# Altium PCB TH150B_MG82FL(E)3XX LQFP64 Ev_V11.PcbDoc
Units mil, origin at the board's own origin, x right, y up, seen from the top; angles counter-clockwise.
Board outline 2850 x 2110 mil, 2 copper layers (Top Layer, Bottom Layer); 50 components, 79 nets, 342 pads, 113 vias.
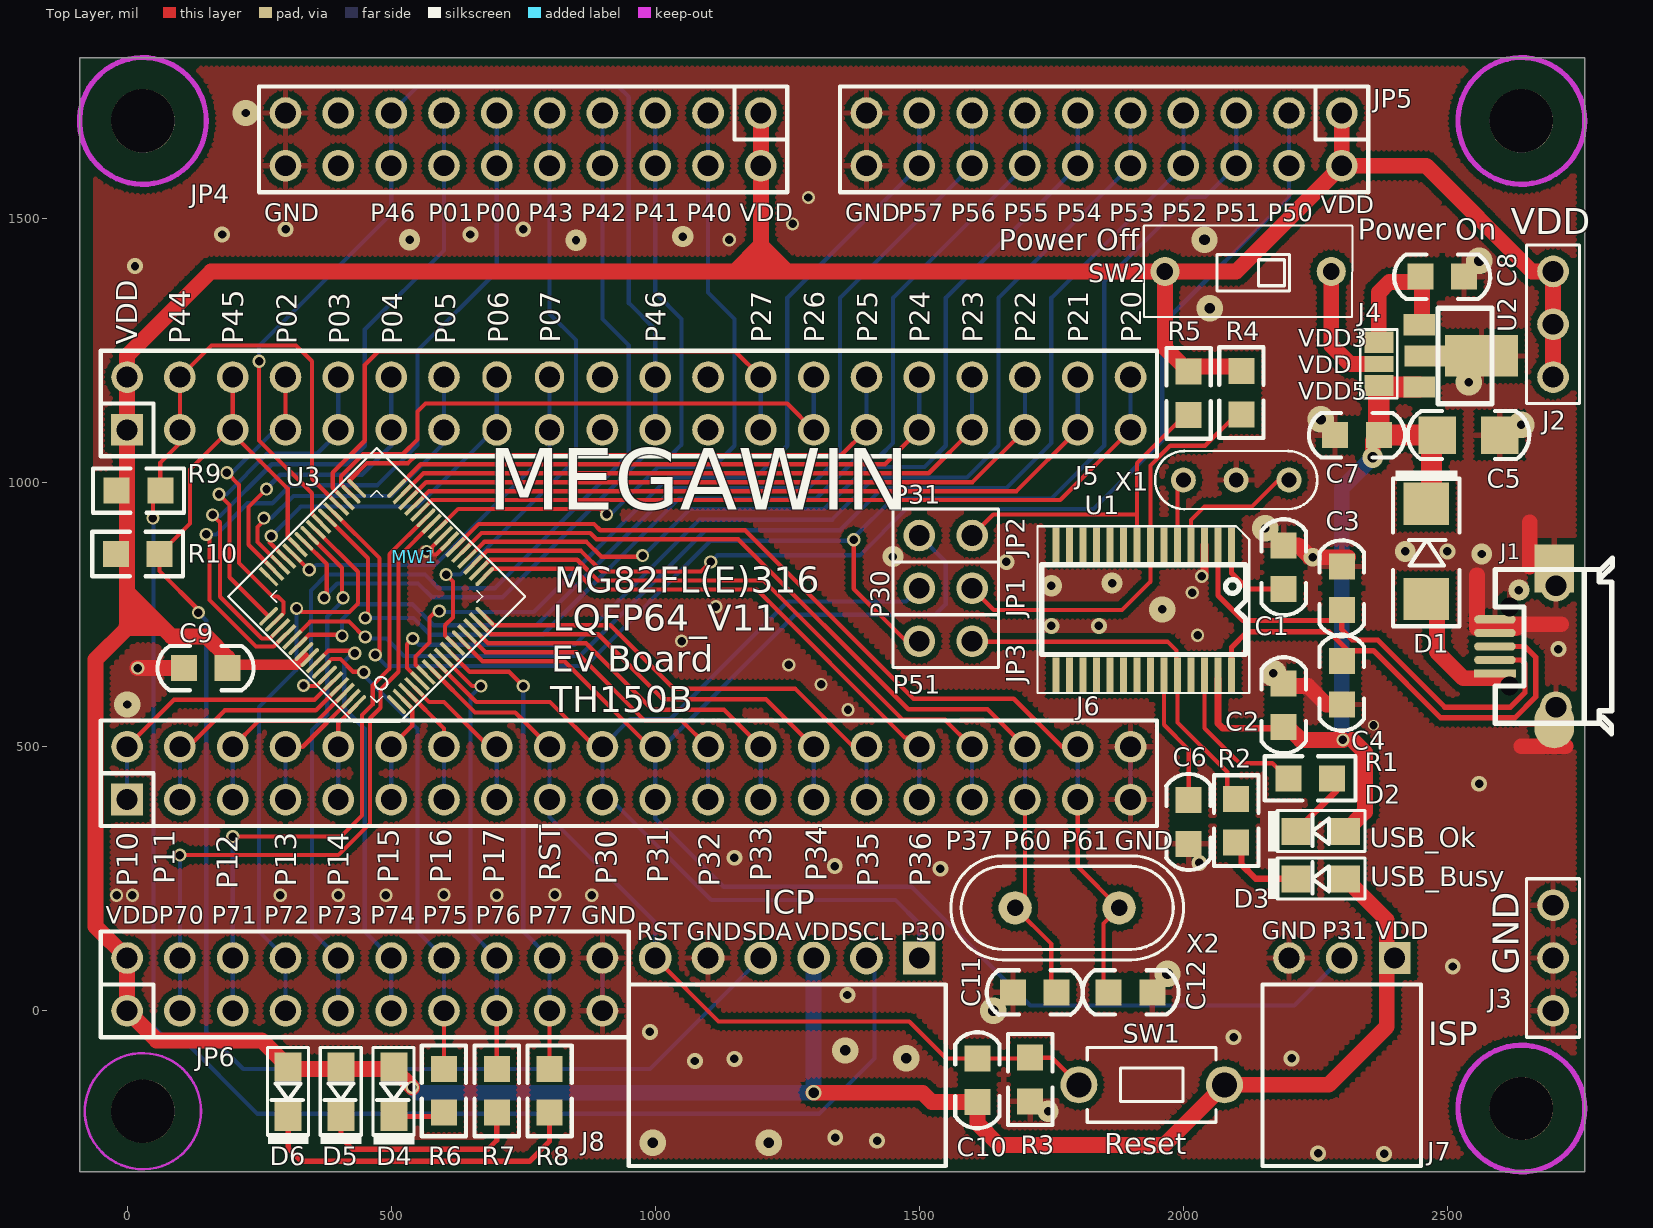
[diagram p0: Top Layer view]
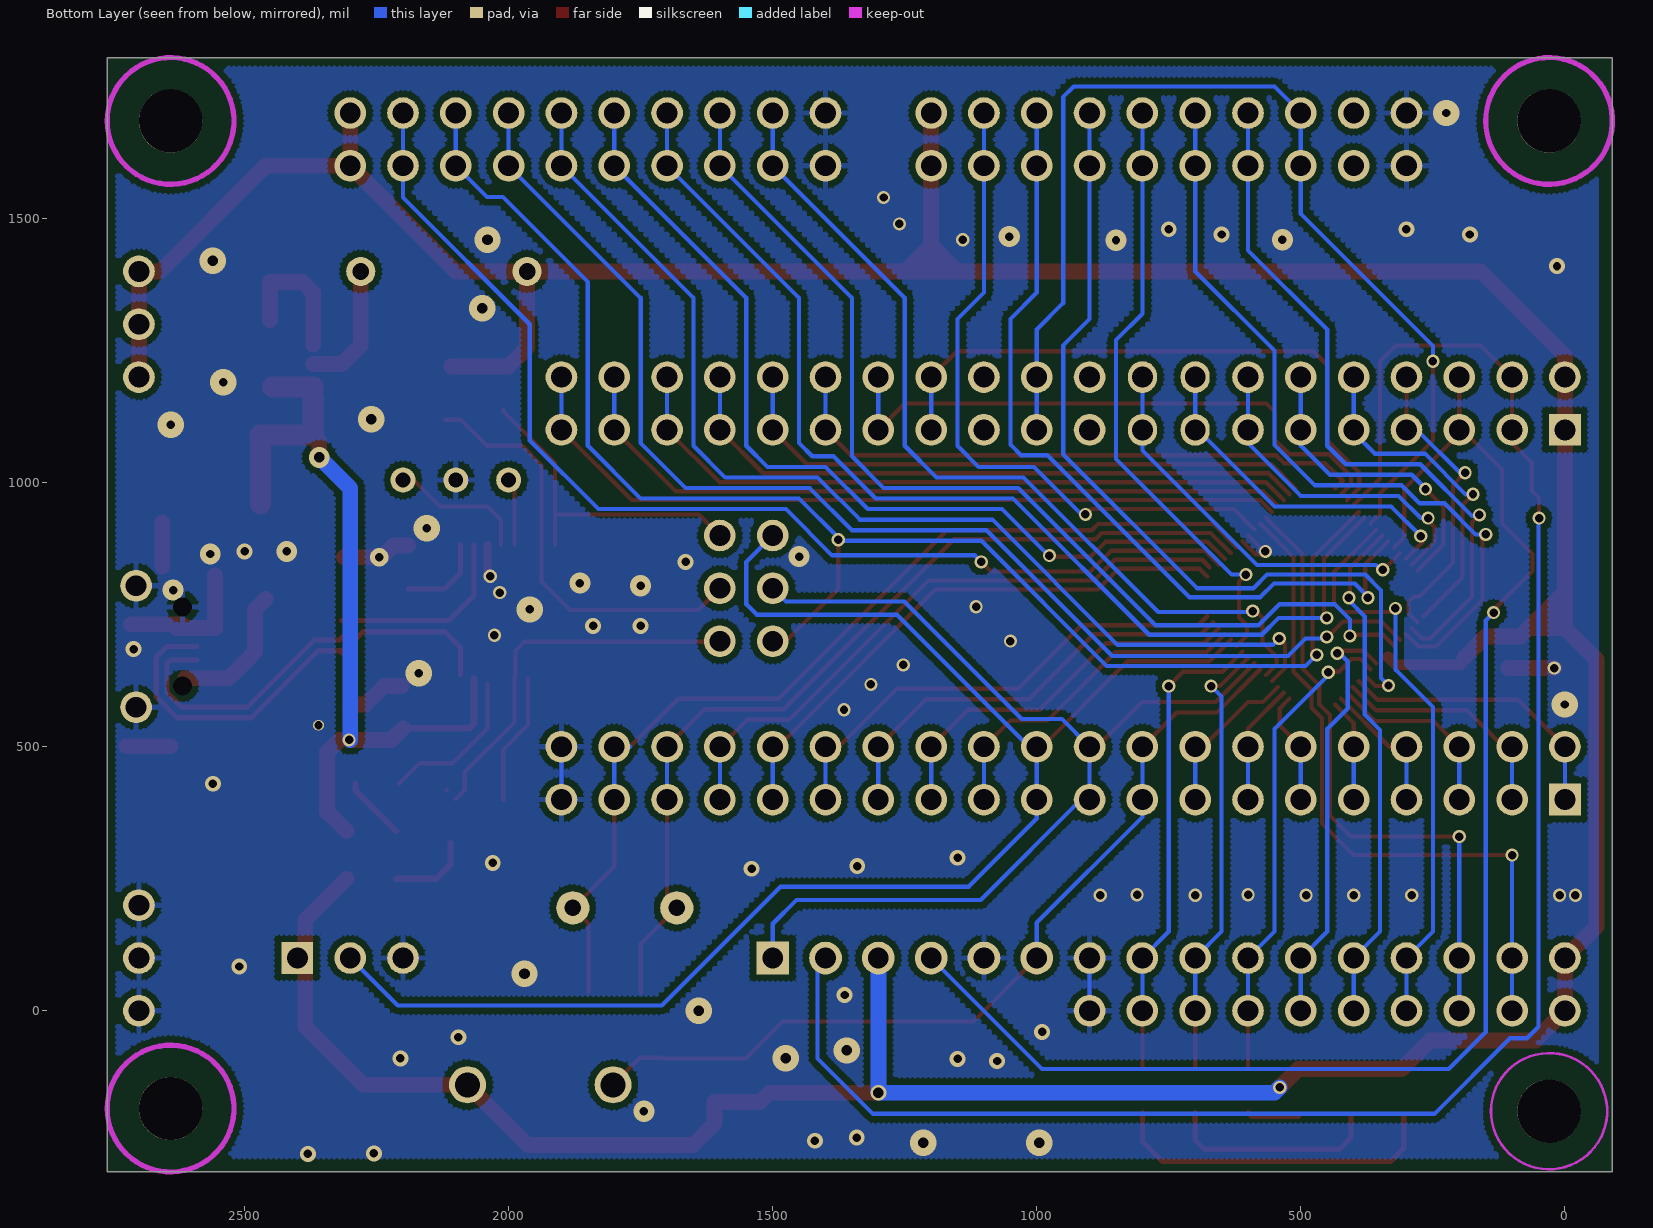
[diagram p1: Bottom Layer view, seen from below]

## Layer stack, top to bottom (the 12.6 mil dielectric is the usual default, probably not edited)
Top Layer: signal copper 1.4
Dielectric: dielectric 12.6, FR-4, Dk 4.8
Bottom Layer: signal copper 1.4

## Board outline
-90,-305 -90,1805 2760,1805 2760,-305

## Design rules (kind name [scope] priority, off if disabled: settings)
Clearance 12 [All] p1 off: gap=12
Clearance 10 [All] p2 off: gap=10
Clearance 6 [All] p3: gap=6
ComponentClearance [All] p1 off: gap=10 collisioncheckmode=3 verticalgap=10 showdistances=FALSE
HoleSize [All] p1: absolutevalues=TRUE maxlimit=500 minlimit=1 maxpercent=80.000 minpercent=20.000
MinimumSolderMaskSliver [All] p1 off: minsoldermaskwidth=10
PolygonConnect VIA [ISVIA] p1: connectstyle=Direct reliefconductorwidth=10 reliefentries=4 polygonreliefangle="90 Angle"
PolygonConnect [All] p2: connectstyle=Relief reliefconductorwidth=10 reliefentries=4 polygonreliefangle="90 Angle"
RoomDefinition "TH150B_MG82FL(E)3XX LQFP64 Ev_V10" [InComponentClass('TH150B_MG82FL(E)3XX LQFP64 Ev_V10')] p1: confinementstyle=ConfineIn formatcopy=TRUE lockcomponents=FALSE outline -505,-825 3205,-825 3205,2185 -505,2185
RoutingVias [All] p1: holewidth=16 width=25 viastyle="Through Hole" minholewidth=16 minwidth=24 maxholewidth=28 maxwidth=50
SilkToSilkClearance [All] p1 off: silktosilkclearance=10
SilkscreenOverComponentPads [All] p1 off: minsilkscreentomaskgap=10
SolderMaskExpansion [All] p1 off: expansion=4
Width [All] p1: maxlimit=200 minlimit=6 preferedwidth=10
23 further rules are at their usual default settings.

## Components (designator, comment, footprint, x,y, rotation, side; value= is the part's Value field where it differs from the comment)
C1 "4.7uF" 0805C 2190,840 r90 top
C2 "0.1uF" 0805C 2190,578.66 r270 top
C3 "15pF" 0805C 2300,800 r90 top
C4 "15pF" 0805C 2300,621.34 r270 top
C5 "4.7uF" 1206C 2540,1090 r0 top
C6 "0.1uF" 0805C 2010,357.66 r90 top
C7 "0.1uF" 0805C 2328.66,1090 r180 top
C8 "4.7uF" 0805C 2490,1390 r0 top
C9 "0.1uF" 0805C 148.66,649 r180 top
C10 "1u" 0805C 1610,-131.34 r90 top
C11 "NC" 0805C 1718.66,35 r180 top
C12 "NC" 0805C 1900,35 r0 top
D1 "1N5817" D5817_SMD_1 2460,870 r270 top
D2 "Yellow" 0805D 2260,340 r180 top
D3 "RED" 0805D 2260,250 r180 top
D4 "Green" 0805D 505,-153.08 r270 top
D5 "RED" 0805D 405,-153.08 r270 top
D6 "Green" 0805D 305,-153.08 r270 top
J1 "Micro USB母座" JACK_USB_SMD290X220P065 2590,690 r180 top
J2 "*" PS3P254 2700,1200 r90 top
J3 "*" PS3P254 2700,200 r270 top
J4 "*" JUMP3_SMD 2370,1225 r90 top
J5 "*" PS20X2P254#1 0,1100 r0 top locked
J6 "*" PS20X2P254#2 0,400 r0 top locked
J7 "*" PS3P254f_90 2400,100 r180 top
J8 "*" PS6P254F_90 1500,100 r180 top
JP1 "JUMPER2" PS2P254 1500,800 r0 top
JP2 "JUMPER2" PS2P254 1500,900 r0 top
JP3 "JUMPER2" PS2P254 1500,700 r0 top
JP4 "*" PS10X2P254 1200,1700 r180 top
JP5 "*" PS10X2P254 2300,1700 r180 top
JP6 "*" PS10X2P254 0,0 r0 top
MW1 "MW-A4" MEGAWIN_T 543.33,860 r0 top
R1 "1K" 0805R 2240,440 r0 top
R2 "1K" 0805R 2100,360 r270 top
R3 "47K" 0805R 1710,-130 r90 top
R4 "4.7K" 0805R 2110,1170.46 r270 top
R5 "4.7K" 0805R 2010,1169.12 r270 top
R6 "1K" 0805R 600,-151.34 r270 top
R7 "1K" 0805R 700,-151.34 r270 top
R8 "1K" 0805R 800,-151.34 r270 top
R9 "4.7K" 0805R 21.66,985 r180 top
R10 "4.7K" 0805R 20,865 r180 top
SW1 "SW TACT-SPST" SW_T_2P 1940,-140 r180 top
SW2 "-" DIP2_SW 2280,1400 r180 top
U1 "MA101_TSSOP28" TSSOP28_170P065 1924.84,759.52 r180 top
U2 "AIC1734-33(SOT-89)" SOT89 2446.53,1240 r270 top
U3 "MG82Fx308/316(LQFP-64)" QFP64_7X7P040 472.58,784.62 r135 top locked (schematic designator U1)
X1 "6MHz" X3P 2200,1005 r180 top
X2 "NC" X49U 1780,195 r0 top

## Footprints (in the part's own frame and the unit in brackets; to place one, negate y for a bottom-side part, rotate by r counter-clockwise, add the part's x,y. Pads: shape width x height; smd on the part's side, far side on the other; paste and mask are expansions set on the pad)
0805C [mm]
  rect 1.25x1.25 smd: 1(-1.05,0) 2(1.05,0)
  silkscreen extent -2.31,-1.07 2.31,1.07
0805D [mm]
  rect 1.4x1.3 smd: 1(-1.192,0) 2(1.192,0)
  silkscreen extent -2.12,-1 2.53,0.98
0805R [mm]
  rect 1.25x1.25 smd: 1(-1.05,0) 2(1.05,0)
  silkscreen extent -2.18,-1.07 2.18,1.07
1206C [mm]
  rect 1.8x1.8 smd: 1(-1.5,0) 2(1.5,0)
  silkscreen extent -2.92,-1.15 2.92,1.16
D5817_SMD_1 [mil]
  rect 80x86.61 smd: 1(90,0) 2(-90,0)
  silkscreen extent -153,-63 142,63
DIP2_SW [mm]
  round 1.4 hole 0.8: 1(0,0) 2(8,0)
  silkscreen extent -1.02,-2.2 9.02,2.2
JACK_USB_SMD290X220P065 [mm]
  rect 1.9x1.8 on Mech2: 0(-2.85,-1.15) 0(-2.85,1.15)
  round 0.8 hole 0.9 unplated: 1(-0.7,1.9) 5(-0.7,-1.9)
  rect 2x0.4 smd: 1(0,1.3)
  oval 2x0.4 smd: 2(0,0.65) 3(0,0) 4(0,-0.65) 5(0,-1.3)
  round 1.524 hole 1: 5(-2.931,2.921) 5(-2.931,-2.921)
  oval 1.9x2.3 smd: 5(-2.85,3.75)
  rect 1.9x2.3 smd: 5(-2.85,-3.75)
  silkscreen extent -5.65,-4.25 -0.01,4.2
JUMP3_SMD [mil]
  rect 40x55 smd: 1(-41,0) 3(41,0)
  rect 30x55 smd: 2(0,0)
  silkscreen extent -65,-35 65,35
MEGAWIN_T [mil]
PS2P254 [mil]
  round 60 hole 39.37: 1(0,0) 2(100,0)
  silkscreen extent -50,-50 150,50
PS3P254 [mil]
  round 60 hole 39.37: 1(0,0) 2(100,0) 3(200,0)
  silkscreen extent -50,-50 250,50
PS3P254f_90 [mil]
  rect 60x60 hole 39.37: 1(0,0)
  round 60 hole 39.37: 2(100,0) 3(200,0)
  silkscreen extent -50,50 250,394
PS6P254F_90 [mil]
  rect 62x62 hole 39.37: 1(0,0)
  round 62 hole 39.37: 2(100,0) 3(200,0) 4(300,0) 5(400,0) 6(500,0)
  silkscreen extent -50,50 550,394
PS10X2P254 [mil]
  round 60 hole 39.37: 1(0,0) 2(0,100) 3(100,0) 4(100,100) 5(200,0) 6(200,100) 7(300,0) 8(300,100) 9(400,0) 10(400,100) 11(500,0) 12(500,100) 13(600,0) 14(600,100) 15(700,0) 16(700,100) 17(800,0) 18(800,100) 19(900,0) 20(900,100)
  silkscreen extent -50,-50 950,150
PS20X2P254#1 [mil]
  rect 60x60 hole 39.37: 1(0,0)
  round 60 hole 39.37: 2(0,100) 3(100,0) 4(100,100) 5(200,0) 6(200,100) 7(300,0) 8(300,100) 9(400,0) 10(400,100) 11(500,0) 12(500,100) 13(600,0) 14(600,100) 19(900,0) 20(900,100) 21(1000,0) 22(1000,100) 23(1100,0) 24(1100,100) 25(1200,0) 26(1200,100) 27(1300,0) 28(1300,100) 29(1400,0) 30(1400,100) 31(1500,0) 32(1500,100) 33(1600,0) 34(1600,100) 35(1700,0) 36(1700,100) 37(1800,0) 38(1800,100) 39(1900,0) 40(1900,100)
  oval 55x60 hole 39.37: 15(700,0) 16(700,100) 17(800,0) 18(800,100)
  silkscreen extent -50,-50 1950,150
PS20X2P254#2 [mil]
  rect 60x60 hole 39.37: 1(0,0)
  round 60 hole 39.37: 2(0,100) 3(100,0) 4(100,100) 5(200,0) 6(200,100) 7(300,0) 8(300,100) 9(400,0) 10(400,100) 11(500,0) 12(500,100) 13(600,0) 14(600,100) 15(700,0) 16(700,100) 17(800,0) 18(800,100) 19(900,0) 20(900,100) 21(1000,0) 22(1000,100) 23(1100,0) 24(1100,100) 25(1200,0) 26(1200,100) 27(1300,0) 28(1300,100) 29(1400,0) 30(1400,100) 31(1500,0) 32(1500,100) 33(1600,0) 34(1600,100) 35(1700,0) 36(1700,100) 37(1800,0) 38(1800,100) 39(1900,0) 40(1900,100)
  silkscreen extent -50,-50 1950,150
QFP64_7X7P040 [mm]
  oval 1.2x0.19 smd: 1(-4.35,3) 12(-4.35,-1.4) 16(-4.35,-3) 33(4.35,-3) 34(4.35,-2.6) 38(4.35,-1) 41(4.35,0.2) 42(4.35,0.6)
  rect 1.2x0.19 smd: 2(-4.35,2.6) 3(-4.35,2.2) 4(-4.35,1.8) 5(-4.35,1.4) 6(-4.35,1) 7(-4.35,0.6) 8(-4.35,0.2) 9(-4.35,-0.2) 10(-4.35,-0.6) 11(-4.35,-1) 13(-4.35,-1.8) 14(-4.35,-2.2) 15(-4.35,-2.6) 35(4.35,-2.2) 36(4.35,-1.8) 37(4.35,-1.4) 39(4.35,-0.6) 40(4.35,-0.2) 43(4.35,1) 44(4.35,1.4) 45(4.35,1.8) 46(4.35,2.2) 47(4.35,2.6) 48(4.35,3)
  oval 0.19x1.2 smd: 17(-3,-4.35) 27(1,-4.35) 32(3,-4.35) 49(3,4.35) 50(2.6,4.35) 54(1,4.35) 55(0.6,4.35) 56(0.2,4.35) 58(-0.6,4.35) 59(-1,4.35) 64(-3,4.35)
  rect 0.19x1.2 smd: 18(-2.6,-4.35) 19(-2.2,-4.35) 20(-1.8,-4.35) 21(-1.4,-4.35) 22(-1,-4.35) 23(-0.6,-4.35) 24(-0.2,-4.35) 25(0.2,-4.35) 26(0.6,-4.35) 28(1.4,-4.35) 29(1.8,-4.35) 30(2.2,-4.35) 31(2.6,-4.35) 51(2.2,4.35) 52(1.8,4.35) 53(1.4,4.35) 57(-0.2,4.35) 60(-1.4,4.35) 61(-1.8,4.35) 62(-2.2,4.35) 63(-2.6,4.35)
  silkscreen extent -5.05,-5.05 5.05,5.05
SOT89 [mm]
  rect 1.016x1.5 smd: 1(-1.5,0) 3(1.5,0)
  rect 2x3.5 smd: 2(0,3)
  rect 1.016x2.6 smd: 2(0,0.6)
  silkscreen extent -2.3,0.9 2.3,3.5
SW_T_2P [mil]
  round 70 hole 47.24: 1(-137.79,0) 2(137.79,0)
  silkscreen extent -122,-71 122,71
TSSOP28_170P065 [mil]
  rect 13x65 smd: 1(-166.34,-123) 2(-140.75,-123) 3(-115.16,-123) 4(-89.57,-123) 5(-63.98,-123) 6(-38.39,-123) 7(-12.79,-123) 8(12.8,-123) 9(38.39,-123) 10(63.98,-123) 11(89.57,-123) 12(115.16,-123) 13(140.75,-123) 14(166.34,-123) 15(166.34,123) 16(140.75,123) 17(115.16,123) 18(89.57,123) 19(63.98,123) 20(38.39,123) 21(12.8,123) 22(-12.79,123) 23(-38.39,123) 24(-63.98,123) 25(-89.57,123) 26(-115.16,123) 27(-140.75,123) 28(-166.34,123)
  silkscreen extent -200,-158 201,158
X3P [mm]
  round 1.2 hole 0.711: 1(0,0) 2(5.08,0) 3(2.54,0)
  silkscreen extent -1.36,-1.4 6.44,1.4
X49U [mm]
  round 1.6 hole 0.8: 1(-2.5,0) 2(2.5,0)
  silkscreen extent -5.6,-2.5 5.6,2.5

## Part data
C1 C5 C8: library part CAP
C2 C3 C4 C6 C7 C9: library part "CAP NP"
C10: library part C
C11 C12: library part "C NP"
D1: library part DIODE_ZD, "Schottky Diode"
D2 D3 D4 D5 D6: library part LED
J1: library part CON5, "Connector"
J2 J3 J4 J7: library part CON3
J5 J6: library part CON40A
J8: library part CON6
JP4 JP5 JP6: library part CON10X2
R1 R2 R4 R5 R6 R7 R8: library part R_Dup1
R3 R9 R10: library part R
SW2: library part SW-2
U2: library part AIC1734-33(SOT-89)_0
U3: library part MG82Fx3xx_0
X1: library part CRYSTAL_RC
X2: library part CRYSTAL

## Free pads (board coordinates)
  round 120 hole 120 unplated: 0(30,-190) 0(30,1685) 0(2640,-185) 0(2640,1685)

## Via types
v1: diameter 25, hole 16, Top Layer to Bottom Layer, tented both sides, 56 vias
v2: diameter 30, hole 16, Top Layer to Bottom Layer, tented both sides, 26 vias
v3: diameter 50, hole 20, Top Layer to Bottom Layer, tented both sides, 10 vias
v4: diameter 40, hole 16, Top Layer to Bottom Layer, tented both sides, 8 vias
v5: diameter 50, hole 16, Top Layer to Bottom Layer, tented both sides, 7 vias
v6: diameter 39.37, hole 16, Top Layer to Bottom Layer, tented both sides, 2 vias
v7: diameter 39.37, hole 20, Top Layer to Bottom Layer, tented both sides, 1 vias
v8: diameter 20, hole 16, Top Layer to Bottom Layer, tented both sides, 1 vias
v9: diameter 35, hole 16, Top Layer to Bottom Layer, tented both sides, 1 vias
v10: diameter 30, hole 20, Top Layer to Bottom Layer, tented both sides, 1 vias

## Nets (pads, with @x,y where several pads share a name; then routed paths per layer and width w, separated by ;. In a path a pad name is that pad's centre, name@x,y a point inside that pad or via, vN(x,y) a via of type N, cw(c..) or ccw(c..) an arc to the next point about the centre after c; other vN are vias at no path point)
D+: C4.1 J1.3 U1.28 | length 893.6
  Top Layer w10: U1.28 2091.18,688.18 2121,718 2275.34,718 C4.1@2311.34,682 ; C4.1@2308,682 C4.1@2311.34,682 ; C4.1@2315.33,678.01 C4.1@2311.34,682 ; J1.3 2646.93,690 2667,669.93 2667,594.28 2627.72,555 2486.72,555 2359.72,682 C4.1@2311.34,682
D-: C3.1 J1.2 U1.2 | length 924.6
  Top Layer w10: U1.2 2065.59,786.25 2112.84,739 C3.1@2300,739 ; C3.1@2300,746 C3.1@2300,739 ; C3.1@2316,739 C3.1@2300,739 ; J1.2 2640.43,664.41 2647,657.84 2647,602.56 2619.44,575 2495,575 2368,702 2320,702 2300,722 C3.1@2300,739
GND_POWER: C1.2 C2.1 C3.2 C4.2 C5.2 C6.1 C7.2 C8.2 C9.2 C11.2 C12.2 J1.4 J1.5 J3.1 J3.2 J3.3 J6.39 J6.40 J7.3 J8.5 JP4.19 JP4.20 JP5.19 JP5.20 JP6.19 JP6.20 R3.1 U1.3 U2.2 U3.23 U3.24 X1.3 | length 1110.9
  Top Layer w8: v1@572,864 584.9,864 ; v1@577.4,868.92 577.4,878.29 U3.24 ; 586.77,865.4 U3.23
  Top Layer w15: v1@2040,823 U1.3
  Top Layer w30: v1(20,649) C9.2 ; C1.2 2217.66,881.34 2240,859 v9(2245,859) C3.2@2312,859 ; C2.1@2203,615 2236,615 2271,580 C4.2 ; 2555.87,725.05 2629.29,725.05 ; 2555.87,727.64 2555.87,824.72 ; 2618.54,732.05 2715.63,732.05 ; 2640.28,500.87 2723.82,500.87 ; 2655.87,841.18 2655.87,924.72
  Bottom Layer w8: JP6.19 JP6.20 ; J6.39 J6.40
  other v1: -20,219 10,219 290,219 400,219 490,219 700,219 880,219 600,220 810,220 1365,570 1314,618 1253,655 1050,700 2027,711 1115,765 2017,792 2035,823 567,870 1140,1460 1260,1490 1290,1540
  other v2: 2380,-271 2255,-270 1420,-246 1341,-240 1075,-95 1150,-91 2205,-90 2095,-50 990,-40 1364,30 2510,84 1540,269 1340,274 2030,280 1150,290 2560,430 2710,685 1750,729 1840,729 1665,850 2500,870 15,1410 180,1470 650,1470 300,1480 750,1480
  other v3: 995,-250 1215,-250 1475,-90 1360,-75 1640,0 1970,70 2260,1120 2050,1330 2560,1420 2040,1460
  other v4: 1744,-190 2635.29,796.72 1750,805 1865,810 1450,860 850,1459 535,1460 1052,1466
  other v5: 0,580 2170,639 1960,760 2155,914 2640,1110 2540,1190 225,1700
  other v6: 2565,865 2420,870
  other v8: 2360,541
MA101_RX: JP2.2 R5.2 U1.8 | length 624.3
  Top Layer w8: JP2.2 1640,940 1912.05,940 ; U1.8 1912.05,940 ; R5.2@2010,1137.66 2010,1135 1912.05,1037.05 1912.05,940
MA101_TX: JP1.2 R4.2 U1.7 | length 815
  Top Layer w8: JP1.2 1641,759 1884,759 1937.64,812.64 1937.64,1032.64 1975,1070 2041,1070 2090,1119 R4.2@2120,1119
NetC1_1: C1.1 U1.1 | length 165
  Top Layer w10: U1.1 2091.18,828.82 2121.34,798.66 C1.1
NetC6_2: C6.2 U1.23 | length 249.4
  Top Layer w8: U1.23@1963.23,629 1963.23,541.77 2010,495 C6.2
NetD1_1: D1.1 J1.1 | length 261.3
  Top Layer w30: D1.1 2480,760 2480,680 2530.28,629.72 J1.1@2612.2,629.72
NetD2_2: D2.2 R1.2 | length 121.9
  Top Layer w12: D2.2 2290,416.92 R1.2@2290,430
NetD3_2: D3.2 R2.2 | length 154.9
  Top Layer w12: R2.2@2110,317.66 2110,277 2137,250 D3.2
NetD4_2: D4.2 R6.2 | length 98
  Top Layer w10: D4.2 592.68,-200 R6.2
NetD5_2: D5.2 R7.2 | length 403.5
  Top Layer w10: D5.2 405,-240 427,-262 683,-262 700,-245 R7.2
NetD6_2: D6.2 R8.2 | length 635.4
  Top Layer w10: D6.2 305,-260 330,-285 762,-285 800,-247 R8.2
NetJ4_2: J4.2 SW2.1 | length 244.5
  Top Layer w30: SW2.1 2280,1260 2315,1225 J4.2
NetU1_4: U1.4 X1.1 | length 263.8
  Top Layer w8: U1.4 2014.41,929.41 2040,955 2130,955 2180,1005 X1.1
NetU1_5: U1.5 X1.2 | length 127.1
  Top Layer w8: U1.5 1988.82,993.82 X1.2
P00: JP4.11 JP4.12 U3.52 | length 1476.5
  Top Layer w8: v1@156,902 156,778 244,690 277.75,690 U3.52
  Bottom Layer w8: v1(150,902) 169,902 228,961 275,961 309,995 473.5,995 550,1071.5 550,1250 700,1400 JP4.12 JP4.11
P01: JP4.13 JP4.14 U3.51 | length 1352
  Top Layer w8: v1(162,939) 176,925 176,784 255,705 270.48,705 U3.51
  Bottom Layer w8: v1(162,939) 164,937 176,937 274,1035 415,1035 450,1070 450,1290 600,1440 JP4.14 JP4.13
P02: J5.7 J5.8 U3.50 | length 559.8
  Top Layer w8: v1(189,1019) 212,996 212,848 275.38,784.62 285.38,784.62 296,774 296,752.8 U3.50 ; J5.7@300,1125 J5.8
  Bottom Layer w8: v1(189,1019) 199,1019 280,1100 J5.7
P03: J5.9 J5.10 U3.49 | length 649.4
  Top Layer w8: v1(174,978) 194,958 194,821 U3.49
  Bottom Layer w8: v1(174,978) 188,978 265,1055 360,1055 400,1095 J5.9 J5.10
P04: J5.11 J5.12 U3.47 | length 589.3
  Top Layer w8: v1(264,988) 230,954 230,882.44 U3.47
  Bottom Layer w8: v1@263.5,988.5 290,1015 445,1015 500,1070 J5.11 J5.12
P05: J5.13 J5.14 U3.46 | length 634.8
  Top Layer w8: v1@261.5,930.5 247,916 247,887.71 U3.46
  Bottom Layer w8: v1(259,933) 273,933 315,975 500,975 600,1075 J5.13 J5.14
P06: J5.15 J5.16 U3.45 | length 649.6
  Top Layer w8: v1@270,886.98 U3.45
  Bottom Layer w8: v1(273,899) 329,955 550,955 J5.15@695,1100 ; J5.15 J5.16
P07: J5.17 J5.18 U3.44 | length 734
  Top Layer w8: U3.44 v1@344.62,834.62
  Bottom Layer w8: v1@345.5,831.5 358,844 583,844 800,1061 J5.17 J5.18
  other v1: 345,835
P10: J6.1 J6.2 U3.60 | length 542
  Top Layer w8: J6.2 89,589 354.92,589 U3.60
  Bottom Layer w8: J6.1 J6.2
P11: J6.3 J6.4 U3.61 | length 448.6
  Top Layer w8: J6.4@116,500 185,569 357.19,569 U3.61
  Bottom Layer w8: J6.3 J6.4 J6.4@116,500
P12: J6.5 J6.6 U3.62 | length 355.1
  Top Layer w8: J6.6 249,549 359.46,549 U3.62
  Bottom Layer w8: J6.5 J6.6
P13: J6.7 J6.8 U3.63 | length 261.6
  Top Layer w8: J6.8 332.73,500 U3.63
  Bottom Layer w8: J6.7 J6.8
P14: J6.9 J6.10 U3.64 | length 215.7
  Top Layer w8: J6.10 400,545 U3.64 U3.64@420,565
  Bottom Layer w8: J6.9 J6.10
P15: J6.11 J6.12 U3.2 | length 243.7
  Top Layer w8: J6.12@520,520 J6.12 540,540 540,572.44 U3.2
  Bottom Layer w8: J6.11 J6.12
P16: J6.13 J6.14 U3.3 | length 230.6
  Top Layer w8: U3.3 600,534.71 J6.14
  Bottom Layer w8: J6.14@599.71,500 J6.14 J6.13
P17: J6.15 J6.16 U3.4 | length 303.4
  Top Layer w8: U3.4 571.98,585 600,585 J6.16@685,500
  Bottom Layer w8: J6.16@685,500 J6.16 J6.15
P20: J5.39 J5.40 U3.28 | length 1509.6
  Top Layer w8: U3.28 577.02,967 1767,967 J5.39
  Bottom Layer w8: J5.39 J5.40
P21: J5.37 J5.38 U3.29 | length 1416.1
  Top Layer w8: U3.29 571.75,984 1684,984 J5.37
  Bottom Layer w8: J5.37 J5.38
P22: J5.35 J5.36 U3.30 | length 1322.7
  Top Layer w8: U3.30 566.48,1001 1601,1001 J5.35
  Bottom Layer w8: J5.35 J5.36
P23: J5.33 J5.34 U3.31 | length 1253.1
  Top Layer w8: 538.2,995 U3.31 561.2,1018 1518,1018 J5.33
  Bottom Layer w8: J5.33 J5.34
P24: J5.31 J5.32 U3.32 | length 1135.7
  Top Layer w8: U3.32 555.93,1035 1435,1035 J5.31
  Bottom Layer w8: J5.31 J5.32
P25: J5.29 J5.30 U3.33 | length 1139.5
  Top Layer w8: U3.33 420.75,1003.48 420.75,1003.75 454,1037 532,1037 547,1052 1352,1052 J5.29
  Bottom Layer w8: J5.29 J5.30
P26: J5.27 J5.28 U3.34 | length 1145.8
  Top Layer w8: U3.34 405,996.96 405,1012.27 446.73,1054 522,1054 550,1082 550,1135 565,1150 1250,1150 J5.27
  Bottom Layer w8: J5.27 J5.28
P27: J5.25 J5.26 U3.35 | length 1172
  Top Layer w8: U3.35 389.25,990.44 389.25,1018.79 450,1079.54 450,1223 476,1249 1151,1249 J5.26
  Bottom Layer w8: J5.25 J5.26
P30_RXD: J6.19 J6.20 J8.1 JP1.1 U3.8 | length 1955.7
  Top Layer w8: U3.8 661.06,585 801,585 J6.20@893,493
  Bottom Layer w8: J6.20@893,493 900,486 J6.19 916,400 1106,210 1455,210 1500,165 J8.1 ; J6.20 952.5,552.5 1028.5,552.5 1251,775 1475,775 JP1.1
P31_TXD: J6.21 J6.22 J7.2 JP2.1 U3.12 | length 2848.7
  Top Layer w8: U3.12 673.15,662 828,662 J6.22@995,495
  Bottom Layer w8: J6.22@1000,490 J6.21 1000,364 1129,235 1485,235 1710,10 2210,10 J7.2 ; J6.22@1020,505 1265,750 1530,750 1550,770 1550,850 JP2.1
P32: J6.23 J6.24 U3.13 | length 644.7
  Top Layer w8: U3.13 678.42,679 851,679 980,550 1050,550 J6.24
  Bottom Layer w8: J6.23 J6.24
P33: J6.25 J6.26 U3.14 | length 777.4
  Top Layer w8: 682.69,697 U3.14 683.69,696 869,696 995,570 1130,570 J6.26
  Bottom Layer w8: J6.25 J6.26
P34: J6.27 J6.28 U3.15 | length 831.6
  Top Layer w8: U3.15 688.96,713 892,713 1015,590 1210,590 J6.28
  Bottom Layer w8: J6.27 J6.28
P35: J6.29 J6.30 U3.16 | length 930.3
  Top Layer w8: U3.16@691.23,733 U3.16 694.23,730 915,730 1035,610 1265,610 J6.30@1387.5,487.5
  Bottom Layer w8: J6.30@1387.5,487.5 1400,475 J6.29
P36: J6.31 J6.32 U3.17 | length 1052.3
  Top Layer w8: U3.17 692,837 845.34,837 884.58,797.77 1192.23,797.77 1472.2,517.8 J6.32@1491.2,517.8
  Bottom Layer w8: J6.31 J6.32
P37: J6.33 J6.34 U3.18 | length 1179.7
  Top Layer w8: U3.18@672.73,840 686.73,854 852.38,854 891.62,814.77 1205.23,814.77 1468.97,551.03 1548.97,551.03 J6.34
  Bottom Layer w8: J6.33 J6.34
P40: JP4.3 JP4.4 U3.25 | length 1286.6
  Top Layer w8: U3.25 626.83,950 896,950 v1@906,940
  Bottom Layer w8: v1@906,940 v1(908,940) 915,940 1005,1030 1110,1030 1150,1070 1150,1310 1100,1360 JP4.4 JP4.3
P41: JP4.5 JP4.6 U3.42 | length 1597.2
  Top Layer w8: U3.42 378,845.79 378,789 v1@371,782
  Bottom Layer w8: v1@371,782 398,809 551,809 577,783 711,783 980,1052 1030,1052 1050,1072 1050,1310 1000,1360 JP4.6 JP4.5
  other v1: 373,782
P42: JP4.7 JP4.8 U3.59 | length 1636.8
  Top Layer w8: v1@334,615 358.64,615 U3.59
  Bottom Layer w8: v1(334,616) 348,630 348,796 378,826 564,826 590,800 696,800 950,1054 950,1260 900,1310 JP4.8 JP4.7
P43: JP4.9 JP4.10 U3.11 | length 1166.8
  Top Layer w8: v1(604,826) 617,813 617,745 602,730 602,710.88 U3.11
  Bottom Layer w8: v1(604,826) 631,826 850,1045 850,1270 800,1320 JP4.10 JP4.9
P44: J5.3 J5.4 J8.2 R9.1 U3.36 | length 3506.2
  Top Layer w8: v1(49,933) 49,971 R9.1 63,1038 100,1075 J5.3 J5.4 160,1260 320,1260 350,1230 350,1007.42 U3.36
  Bottom Layer w8: v1(49,933) 50,932 50,-30 72,-52 104,-52 247,-195 1310,-195 1415,-90 J8.2@1415,105
P45: J5.5 J5.6 J8.4 R10.1 U3.43 | length 2772
  Top Layer w8: v1@137.5,756.5 61.34,832.66 R10.1 119,922.66 119,1025 194,1100 194,1099 304,989 304,897.52 U3.43 ; J5.5 J5.6
  Bottom Layer w8: v1(135,754) 150,739 150,-40 220,-110 990,-110 J8.4
P46: J5.21 J5.22 JP4.15 JP4.16 U3.39 | length 2059.8
  Top Layer w8: v1(250,1230) 250,1080 350,980 350,940.6 U3.39
  Bottom Layer w8: v1(250,1230) 250,1259 500,1509 JP4.16 JP4.15 550,1750 930,1750 950,1730 950,1340 1000,1290 J5.22 J5.21
P50: JP5.3 JP5.4 U3.19 | length 2247.7
  Top Layer w8: U3.19 681.46,871 859.43,871 898.66,831.77 ; 991.77,831.77 898.66,831.77 ; v1(1105,850) 1086.77,831.77 898.66,831.77
  Bottom Layer w8: v1(1105,850) 1117.44,862.44 1387.44,862.44 1475,950 1830,950 1960,1080 1960,1300 2200,1540 JP5.4 JP5.3
P51: JP3.1 JP5.5 JP5.6 U3.37 | length 2882.7
  Top Layer w8: U3.37 478,857.15 478,674 v1@474,670 ; v1(1376,892) 1376,799 1475,700 JP3.1
  Bottom Layer w8: v1@474,670 491,653 868,653 1105,890 v1@1375,890 ; v1(1376,892) v1@1375,890 ; JP5.5 JP5.6 2041.02,1541.02 2011.02,1541.02 1850,1380 1850,1070 1750,970 1450,970 1375,895 v1@1375,890
  other v1: 470,674
P52: JP5.7 JP5.8 U3.53 | length 2374.5
  Top Layer w8: U3.53 347.02,737 420,737 v1@451.5,705.5
  Bottom Layer w8: v1@451,705 491,705 524,672 857,672 1095,910 1350,910 1430,990 1665,990 1750,1075 1750,1350 JP5.8 JP5.7
  other v1: 451,708
P53: JP5.9 JP5.10 U3.5 | length 2098.9
  Top Layer w8: v1(541,705) 530,694 530,649.25 U3.5
  Bottom Layer w8: v1(541,705) 553,693 847,693 1084,930 1335,930 1415,1010 1590,1010 1650,1070 1650,1350 JP5.10 JP5.9
P54: JP5.11 JP5.12 U3.20 | length 1751.8
  Top Layer w8: U3.20 676.19,888 869.92,888 897.92,860 v1@976,860
  Bottom Layer w8: v1@976,860 1066,950 1320,950 1400,1030 1510,1030 1550,1070 1550,1350 JP5.12 JP5.11
  other v1: 976,862
P55: JP5.13 JP5.14 U3.38 | length 2113.5
  Top Layer w8: U3.38 456,856.88 v1@456,743
  Bottom Layer w8: v1(451,744) 542,744 574,712 787,712 1045,970 1305,970 1385,1050 1425,1050 1450,1075 1450,1350 JP5.14 JP5.13
P56: JP5.15 JP5.16 U3.54 | length 1980.6
  Top Layer w8: U3.54 344.29,712 v1@407,712
  Bottom Layer w8: v1(407,710) 407,741 436,770 540,770 580,730 775,730 1035,990 1290,990 1350,1050 1350,1350 JP5.16 JP5.15
P57: JP5.17 JP5.18 U3.6 | length 1677.7
  Top Layer w8: U3.6 546,655.52 546,671 572.5,697.5 572.5,744.5 v1@589,761
  Bottom Layer w8: v1@591,763 599,755 770,755 1025,1010 1190,1010 1250,1070 1250,1350 JP5.18 JP5.17
  other v1: 591,757
P60_X2: C11.1 J6.35 J6.36 U3.21 X2.1 | length 1751.9
  Top Layer w8: U3.21 670.92,905 876.96,905 888.96,893 1157,893 1478.97,571.03 1628.97,571.03 J6.36 ; J6.35 1700,213.42 X2.1 1750,126.58 C11.1@1750,35
  Bottom Layer w8: J6.35 J6.36
P61_X1: C12.1 J6.37 J6.38 U3.22 X2.2 | length 1881.4
  Top Layer w8: U3.22 665.64,922 884,922 896,910 1170,910 1488.97,591.03 1678.97,591.03 J6.38@1770,500 ; J6.37 1800,273.42 X2.2 1848.66,165.24 C12.1@1848.66,35
  Bottom Layer w8: J6.38@1770,500 J6.38 J6.37
P70: JP6.3 JP6.4 U3.26 | length 1295.7
  Top Layer w8: v1(100,295) 400,295 460,355 460,554 480,574 480,608 514,642 514,859.44 U3.26
  Bottom Layer w8: JP6.3 JP6.4 v1(100,295)
P71: JP6.5 JP6.6 U3.27 | length 1205.2
  Top Layer w8: v1(200,330) 405,330 445,370 445,560.21 465,580.21 465,615.88 497,647.88 497,864.71 U3.27
  Bottom Layer w8: JP6.5 JP6.6 v1(200,330)
P72: JP6.7 JP6.8 U3.40 | length 1115.3
  Top Layer w8: v1@321,765 331,755 421,755 437,771 437,831.33 U3.40
  Bottom Layer w8: JP6.7 JP6.8 250,150 250,575 321,646 v1(321,762) v1@321,765
P73: JP6.9 JP6.10 U3.41 | length 995.6
  Top Layer w8: U3.41 407,839.06 v1@407,783
  Bottom Layer w8: JP6.9@400,-25 JP6.9 JP6.10 350,150 350,532 379,561 379,746.71 409,776.71 v1(409,782) ; v1@408,782 v1@408,783
P74: JP6.11 JP6.12 U3.57 | length 812.5
  Top Layer w8: U3.57 381.1,682 v1@432,682
  Bottom Layer w8: v1@432,682 411,661 411,573 450,534 450,150 JP6.12 JP6.11
  other v1: 431,677
P75: JP6.13 JP6.14 R6.1 U3.58 | length 910.9
  Top Layer w8: U3.58 387.37,666 404,666 428,642 v1@448,642 ; R6.1 JP6.13
  Bottom Layer w8: v1@445,639 550,534 550,150 JP6.14 JP6.13
  other v1: 448,641
P76: JP6.15 JP6.16 R7.1 U3.9 | length 847.1
  Top Layer w8: U3.9 653.33,615 v1(670,615) ; R7.1 JP6.15
  Bottom Layer w8: v1(670,615) 650,595 650,150 JP6.16 JP6.15
P77: JP6.17 JP6.18 R8.1 U3.10 | length 962.3
  Top Layer w8: U3.10 648.6,642 723,642 v1(750,615) ; R8.1 JP6.17
  Bottom Layer w8: 750,230 750,280 ; v1(750,615) 750,280 ; JP6.17 JP6.18 750,150 750,280
RST: C10.2 J6.17 J6.18 J8.6 R3.2 SW1.2 U3.7 | length 1669.4
  Top Layer w8: U3.7 658.79,565 735,565 J6.18 ; J8.6 1120,-20 1481,-20 1551,-90 C10.2 1708.66,-90 R3.2 1750.87,-88.66 SW1.2
  Bottom Layer w8: J6.18 J6.17 800,367 1000,167 J8.6
USB_BUSY: JP3.2 R2.1 U1.24 | length 981.1
  Top Layer w8: JP3.2@1601,699 1780,699 ; 1650,699 1780,699 ; 2080,455 1988.82,546.18 ; R2.1 2083,418.34 2083,452 1988.82,546.18 ; R2.1@2116.83,418.17 R2.1@2118,417 ; 1780,699 1970,699 1986.96,682.04 1986.96,634.66 1988.82,632.8 1988.82,546.18
USB_OK: R1.1 U1.26 | length 380.7
  Top Layer w8: U1.26@2040,620 2040,535 ; 2100,475 2040,535 ; R1.1@2207.32,430 2168.32,469 2106,469 2040,535
VDD: C9.1 C10.1 D3.1 D4.1 D5.1 D6.1 J2.1 J2.2 J2.3 J5.1 J5.2 J7.1 J8.3 JP4.1 JP4.2 JP5.1 JP5.2 JP6.1 JP6.2 R4.1 R5.1 R9.2 R10.2 SW1.1 SW2.2 U3.55 U3.56 | length 8968.5
  Top Layer w20: C9.1@196,655 320,655 335,670
  Top Layer w30: -2,725 0,725 ; 39,748 0,748 ; 66,725 0,725 ; C9.1@190,669 150,709 84,709 0,793 ; 263.84,-65 D6.1 ; v1(540,-145) 505,-110 308.84,-110 D6.1 ; JP4.1@1200,1676.32 JP4.2 1200,1450 ; v10(1300,-155) 1506,-155 1523.68,-172.68 C10.1 1610,-213 1651,-254 1963.79,-254 SW1.1 2275,-140 2385,-30 2385,171.92 D3.1 ; R4.1@2108.66,1220.34 2000.12,1220.34 1965.04,1255.42 SW2.2 ; JP5.1 JP5.2 ; J2.1 J2.2 J2.3 2660,1400 2460,1600 JP5.2 ; 0,725 0,748 ; 0,725 -60,665 -60,160 JP6.2 JP6.1 56,-56 254.84,-56 D6.1 ; 0,748 0,793 ; 0,793 J5.1 J5.2 0,1241 159,1400 1150,1400 ; 1150,1400 1200,1450 ; 1150,1400 1200,1400 ; 1200,1400 1200,1450 ; 1200,1400 1250,1400 ; 1200,1450 1250,1400 ; 1250,1400 SW2.2 ; SW2.2 2100,1400 JP5.2
  Bottom Layer w30: v1(540,-145) 550,-155 v10(1300,-155) J8.3
VDD3: C8.1 J4.3 U2.1 | length 256.8
  Top Layer w30: J4.3@2370,1262 J4.3 2370,1360 2390,1380 C8.1@2448.66,1380 ; U2.1@2451.89,1308.11 C8.1@2451.89,1380
VDD5: C2.2 C5.1 C7.1 D1.2 D2.1 J4.1 U1.27 U2.3 | length 1555.4
  Top Layer w13: U1.27@2065.59,629 2065.59,544.41 2075,535 2150,535 ; 2085,535 2150,535 ; C2.2@2200,535 2150,535
  Top Layer w30: C2.2@2200,535 2221.94,513.06 v1(2302,513.06) ; D2.1 2343.66,376.74 2343.66,489.34 2319.94,513.06 ; v7(2358.66,1048) C7.1@2358.66,1078.66
  Top Layer w40: 2370,1160 C7.1 C5.1@2470.94,1090 ; J4.1@2370,1180.94 U2.3 ; D1.2@2470,960 C5.1@2470,1080.94
  Bottom Layer w30: v1@2300,513.06 2300,989.34 v7(2358.66,1048)
pads on no net: J1.0 J5.19 J5.20 J5.23 J5.24 JP4.17 JP4.18 U1.6 U1.9 U1.10 U1.11 U1.12 U1.13 U1.14 U1.15 U1.16 U1.17 U1.18 U1.19 U1.20 U1.21 U1.22 U1.25 U3.1 U3.48

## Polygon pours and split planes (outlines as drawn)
GND_POWER on Bottom Layer "Bottom Layer-No Net" (hatched 90Degree grid 10 track 10, remove dead copper, pour order 1001): -60,-276 2740,-276 2740,1785 -60,1785
GND_POWER on Top Layer "Bottom Layer-No Net" (hatched 90Degree grid 10 track 10, remove dead copper, pour order 1001): -60,-276 2740,-276 2740,1785 -60,1785

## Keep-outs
Keep-Out Layer:
  circle w10: c2640,-185 r120
  circle w10: c30,1685 r120
  circle w5: c30,-190 r110
  circle w10: c2640,1685 r120

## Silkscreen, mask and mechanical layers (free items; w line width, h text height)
Top Overlay:
  text "VDD" at 2260,1510 h33
  text "GND" at 260,1495 h33
  text "P46" at 460,1495 h33
  text "P01" at 570,1495 h33
  text "P00" at 660,1495 h33
  text "P43" at 760,1495 h33
  text "P42" at 860,1495 h33
  text "P41" at 960,1495 h33
  text "P40" at 1060,1495 h33
  text "VDD" at 1160,1495 h33
  text "GND" at 1360,1495 h33
  text "P57" at 1460,1495 h33
  text "P56" at 1560,1495 h33
  text "P55" at 1660,1495 h33
  text "P54" at 1760,1495 h33
  text "P53" at 1860,1495 h33
  text "P52" at 1960,1495 h33
  text "P51" at 2060,1495 h33
  text "P50" at 2160,1495 h33
  text "VDD" at 2620,1470 h50
  text "Power On" at 2330,1460 h40
  text "Power Off" at 1650,1440 h40
  text "P07" at 820,1265 h38 r90
  text "P46" at 1020,1265 h38 r90
  text "P27" at 1220,1265 h38 r90
  text "P26" at 1320,1265 h38 r90
  text "P25" at 1420,1265 h38 r90
  text "P24" at 1520,1265 h38 r90
  text "P23" at 1620,1265 h38 r90
  text "P22" at 1720,1265 h38 r90
  text "P21" at 1820,1265 h38 r90
  text "P20" at 1920,1265 h38 r90
  text "P06" at 722,1264 h38 r90
  text "P44" at 120,1262 h40 r90
  text "P45" at 220,1262 h40 r90
  text "P02" at 321,1262 h38 r90
  text "P03" at 421,1262 h38 r90
  text "P04" at 521,1262 h38 r90
  text "P05" at 621,1262 h38 r90
  text "VDD" at 19,1261 h40 r90
  text "VDD3" at 2217.25,1257 h33
  text "VDD" at 2217.25,1207 h33
  text "VDD5" at 2217.25,1157 h33
  text "P31" at 1450,960 h35
  text "MG82FL(E)316" at 808.66,792 h50
  text "P30" at 1443,743 h35 r90
  text "LQFP64_V11" at 805.66,719.34 h50
  text "Ev Board" at 802.66,642.34 h50
  text "P51" at 1450,600 h35
  text "TH150B" at 801.66,565.34 h50
  text "USB_Ok" at 2353,310 h37
  text "P37" at 1550,305 h35
  text "P60" at 1660,305 h35
  text "P61" at 1770,305 h35.43
  text "GND" at 1870,305 h35.43
  text "RST" at 820,245 h40 r90
  text "P33" at 1220,245 h40 r90
  text "P34" at 1325,245 h40 r90
  text "P15" at 513.95,241.95 h40 r90
  text "P16" at 613.95,241.95 h40 r90
  text "P17" at 713.95,241.95 h40 r90
  text "P31" at 1025,241.5 h40 r90
  text "P11" at 90,240 h40 r90
  text "P30" at 927.42,239.08 h40 r90
  text "USB_Busy" at 2354,236 h37
  text "P10" at 20,235 h40 r90
  text "P13" at 320,235 h40 r90
  text "P14" at 420,235 h40 r90
  text "P32" at 1122,235 h40 r90
  text "P35" at 1422,235 h40 r90
  text "P36" at 1522,235 h40 r90
  text "P12" at 210,230 h40 r90
  text "ICP" at 1205,184 h45
  text "VDD" at -40,165 h33
  text "P70" at 60,165 h33
  text "P71" at 160,165 h33
  text "P72" at 260,165 h33
  text "P73" at 360,165 h33
  text "P74" at 460,165 h33
  text "P75" at 560,165 h33
  text "P76" at 660,165 h33
  text "P77" at 760,165 h33
  text "GND" at 860,165 h33
  text "GND" at 2148,136 h33
  text "P31" at 2263,136 h33
  text "VDD" at 2363,136 h33
  text "RST" at 965,134 h33
  text "GND" at 1060,134 h33
  text "SDA" at 1165,134 h33
  text "VDD" at 1265,134 h33
  text "SCL" at 1365,134 h33
  text "P30" at 1465,134 h33
  text "GND" at 2635,68 h50 r90
  text "ISP" at 2464,-65 h45
  text "Reset" at 1850,-272 h40
Mechanical 1:
  the board outline again, w13

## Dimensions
-90,1805 to -90,-305 on Top Overlay
-90,-305 to 2760,-305 on Top Overlay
